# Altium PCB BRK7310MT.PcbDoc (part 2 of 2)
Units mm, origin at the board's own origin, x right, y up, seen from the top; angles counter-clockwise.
Board outline 140 x 100 mm, 6 copper layers (L1-TOP, L2-GND, L3-SIG, L4-SIG, L5-GND, L6-BOT), stack 1.39 mm thick; 75 components, 182 nets, 687 pads, 296 vias.
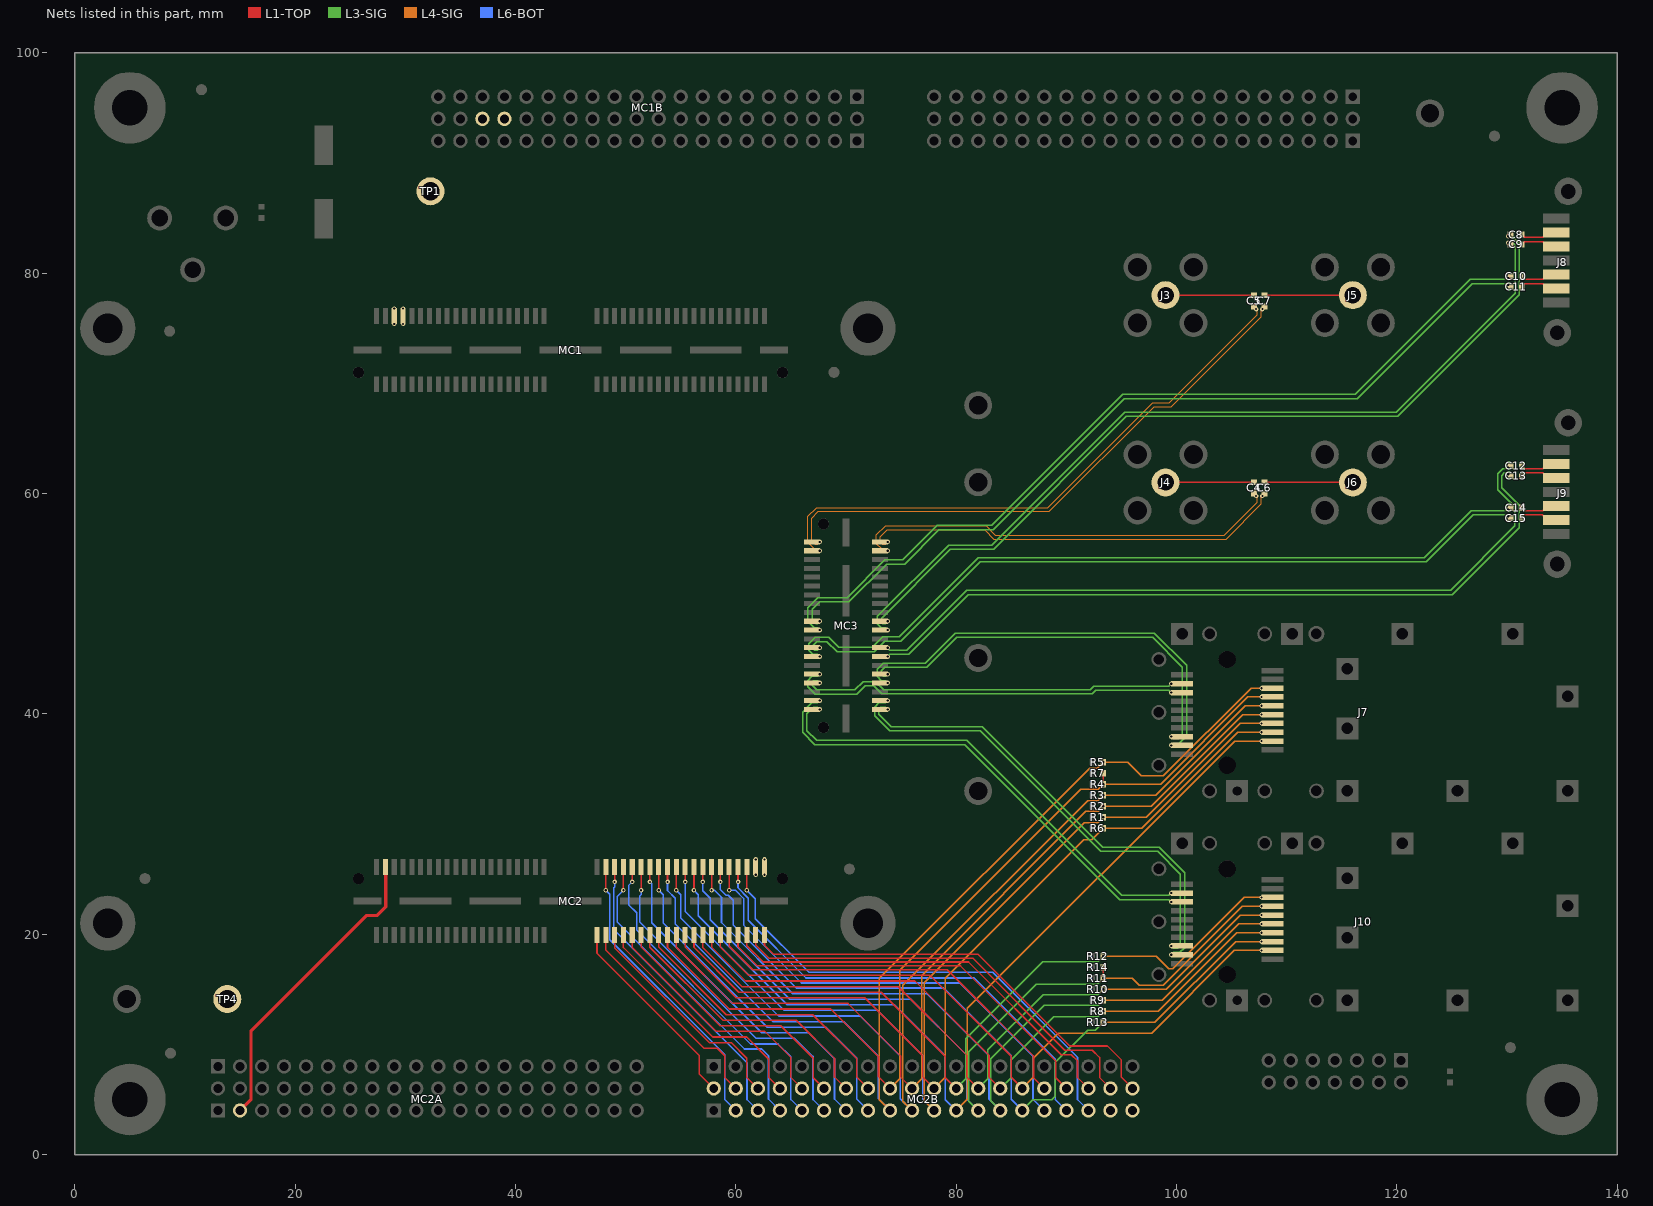
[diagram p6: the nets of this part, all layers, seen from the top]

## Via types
v1: diameter 0.406, hole 0.203, L1-TOP to L6-BOT, tented both sides, 296 vias

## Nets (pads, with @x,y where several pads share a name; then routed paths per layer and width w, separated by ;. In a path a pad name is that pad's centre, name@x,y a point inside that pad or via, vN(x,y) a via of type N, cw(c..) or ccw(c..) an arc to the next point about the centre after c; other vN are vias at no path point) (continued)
MC2_42: MC2.42 MC2B.2 | length 18.5
  L1-TOP w0.146: MC2.42@47.4,20.135 47.4,18.278 56.693,8.986 56.693,7.307 MC2B.2@58,6
MC2_43: MC2.43 MC2B.3 | length 26.8
  L1-TOP w0.146: v1(48.2,23.981) MC2.43@48.2,25.865
  L6-BOT w0.146: v1(48.2,23.981) 48.565,23.617 48.565,19.507 58.979,9.093 58.979,5.021 MC2B.3@60,4
MC2_44: MC2.44 MC2B.4 | length 19.7
  L1-TOP w0.146: MC2.44@48.2,20.135 48.2,18.555 57.103,9.652 58.322,9.652 59,8.974 59,7 MC2B.4@60,6
MC2_45: MC2.45 MC2B.5 | length 27.5
  L1-TOP w0.146: MC2.45@48.971,26.01 49,25.98 v1(49,24.743)
  L6-BOT w0.146: v1(49,24.743) 49,24.29 48.92,24.21 48.92,20.422 61.011,8.331 61.011,4.989 MC2B.5@62,4
MC2_46: MC2.46 MC2B.6 | length 20.7
  L1-TOP w0.146: MC2.46@49,20.135 49,18.745 57.586,10.16 59.592,10.16 61,8.752 61,7 MC2B.6@62,6
MC2_47: MC2.47 MC2B.7 | length 29.1
  L1-TOP w0.146: v1(49.801,23.981) MC2.47@49.801,25.865
  L6-BOT w0.146: v1(49.801,23.981) 49.225,23.406 49.225,21.133 60.782,9.576 62.361,9.576 62.967,8.97 62.967,5.033 MC2B.7@64,4
MC2_48: MC2.48 MC2B.8 | length 21.8
  L1-TOP w0.146: MC2.48@49.801,20.135 49.801,18.783 57.916,10.668 60.989,10.668 63,8.657 63,7 MC2B.8@64,6
MC2_49: MC2.49 MC2B.9 | length 30.2
  L1-TOP w0.146: MC2.49@50.571,26.06 50.601,26.031 v1(50.601,24.743)
  L6-BOT w0.146: v1(50.601,24.743) 50.267,24.409 50.267,22.683 51,21.949 51,20.374 61.341,10.033 63.834,10.033 65,8.867 65,5 MC2B.9@66,4
MC2_50: MC2.50 MC2B.10 | length 23.1
  L1-TOP w0.146: MC2.50@50.601,20.135 50.601,18.796 58.221,11.176 62.64,11.176 65,8.816 65,7 MC2B.10@66,6
MC2_51: MC2.51 MC2B.11 | length 31
  L1-TOP w0.146: v1(51.401,23.981) MC2.51@51.401,25.865
  L6-BOT w0.146: v1@51.342,24.04 v1@51.401,24.1 ; v1(51.401,23.981) 51.401,23.592 51.283,23.473 51.283,21.107 61.849,10.541 65.358,10.541 67.005,8.894 67.005,4.995 MC2B.11@68,4
MC2_52: MC2.52 MC2B.12 | length 24.2
  L1-TOP w0.146: MC2.52@51.401,20.135 51.401,18.851 58.567,11.684 64.088,11.684 67.031,8.741 67.031,6.969 MC2B.12@68,6
MC2_53: MC2.53 MC2B.13 | length 31.9
  L1-TOP w0.146: MC2.53@52.172,25.984 52.201,25.955 v1(52.201,24.743)
  L6-BOT w0.146: v1(52.201,24.743) 52.375,24.569 52.375,21.031 62.357,11.049 66.603,11.049 68.961,8.691 68.961,5.039 MC2B.13@70,4
MC2_54: MC2.54 MC2B.14 | length 25.4
  L1-TOP w0.146: MC2.54@52.201,20.135 52.201,18.821 58.83,12.192 65.485,12.192 68.961,8.716 68.961,7.039 MC2B.14@70,6
MC2_55: MC2.55 MC2B.15 | length 32.8
  L1-TOP w0.146: v1(53.001,23.981) MC2.55@53.001,25.865
  L6-BOT w0.146: v1(53.001,23.981) 53.416,23.566 53.416,21.006 62.865,11.557 68.152,11.557 70.968,8.741 70.968,5.032 MC2B.15@72,4
MC2_56: MC2.56 MC2B.16 | length 26.6
  L1-TOP w0.146: MC2.56@53.001,20.135 53.001,18.834 59.135,12.7 66.984,12.7 70.993,8.691 70.993,7.007 MC2B.16@72,6
MC2_71: MC2.71 MC2B.31 | length 42.5
  L1-TOP w0.146: v1(59.402,23.981) MC2.71@59.402,25.865
  L6-BOT w0.146: v1(59.402,23.981) 59.966,23.981 60.706,23.241 60.706,20.828 65.964,15.57 80.319,15.57 86.97,8.919 86.97,5.03 MC2B.31@88,4
MC2_72: MC2.72 MC2B.32 | length 36.3
  L1-TOP w0.146: MC2.72@59.402,20.135 59.402,18.894 61.531,16.764 79.201,16.764 87.02,8.945 87.02,6.98 MC2B.32@88,6
MC2_73: MC2.73 MC2B.33 | length 43.3
  L1-TOP w0.146: v1(60.202,24.743) 60.202,25.946 MC2.73@60.249,25.993
  L6-BOT w0.146: v1(60.202,24.743) 60.202,24.202 61.138,23.266 61.138,21.26 66.37,16.027 81.636,16.027 89.002,8.661 89.002,4.998 MC2B.33@90,4
MC2_74: MC2.74 MC2B.34 | length 37.1
  L1-TOP w0.146: MC2.74@60.202,19.914 60.202,18.868 61.951,17.12 80.391,17.12 89.027,8.484 89.027,6.973 MC2B.34@90,6
MC2_75: MC2.75 MC2B.35 | length 44.5
  L1-TOP w0.146: v1(61.002,23.981) MC2.75@61.002,25.865
  L6-BOT w0.146: v1(61.002,23.981) 61.773,23.211 61.773,21.412 66.65,16.535 83.312,16.535 91.008,8.839 91.008,4.992 MC2B.35@92,4
MC2_76: MC2.76 MC2B.36 | length 38.2
  L1-TOP w0.146: MC2.76@61.002,19.914 61.002,18.957 62.484,17.475 81.128,17.475 89.535,9.068 90.449,9.068 91.008,8.509 91.008,6.992 MC2B.36@92,6
MC2_78: MC2.78 MC2B.38 | length 39.6
  L1-TOP w0.146: MC2.78@61.802,19.914 61.802,19.021 62.992,17.831 81.509,17.831 89.865,9.474 92.354,9.474 93.015,8.814 93.015,6.985 MC2B.38@94,6
MC2_80: MC2.80 MC2B.40 | length 40.6
  L1-TOP w0.146: MC2.80@62.602,19.914 62.602,19.008 63.449,18.161 81.991,18.161 90.297,9.855 93.726,9.855 94.996,8.585 94.996,7.004 MC2B.40@96,6
MGTREFCLK0N: C4.2 MC3.38 | length 39.2
  L4-SIG w0.107: v1(73.782,54.801) 73.562,55.021 73.18,55.021 72.766,55.435 72.766,56.233 73.587,57.053 82.723,57.053 83.566,56.21 104.341,56.21 107.325,59.194 107.325,59.658 v1(107.213,59.77)
MGTREFCLK0P: C6.2 MC3.40 | length 38.6
  L4-SIG w0.107: v1(73.782,55.601) 73.562,55.381 73.33,55.381 73.127,55.584 73.127,56.083 73.736,56.693 82.573,56.693 83.417,55.85 104.491,55.85 107.686,59.045 107.686,59.658 v1(107.798,59.77)
MGTREFCLK1N: C5.2 MC3.37 | length 52.7
  L4-SIG w0.107: v1(67.61,54.801) 67.39,55.021 67.059,55.021 66.518,55.562 66.518,57.909 67.333,58.725 88.316,58.725 97.82,68.229 99.355,68.229 107.325,76.2 107.325,76.625 v1(107.213,76.737)
MGTREFCLK1P: C7.2 MC3.39 | length 52.1
  L4-SIG w0.107: v1(67.61,55.601) 67.39,55.381 67.208,55.381 66.878,55.711 66.878,57.76 67.483,58.364 88.465,58.364 97.97,67.869 99.504,67.869 107.686,76.051 107.686,76.625 v1(107.798,76.737)
NetC4_1: C4.1 J4.1 | length 8
  L1-TOP w0.133: J4.1@99,61 99.017,61.017 C4.1@107.036,61.017
NetC5_1: C5.1 J3.1 | length 8
  L1-TOP w0.133: J3.1@99,78 99.016,77.984 C5.1@107.036,77.984
NetC6_1: C6.1 J6.1 | length 8
  L1-TOP w0.133: C6.1@107.975,61.017 115.983,61.017 J6.1@116,61
NetC7_1: C7.1 J5.1 | length 8
  L1-TOP w0.133: C7.1@107.975,77.984 115.984,77.984 J5.1@116,78
SATA_1_TXA+: C8.2 MC3.22 | length 77.1
  L3-SIG w0.127: v1(73.782,48.4) 73.573,48.191 73.349,48.191 73.228,48.311 73.228,48.692 79.477,54.94 83.388,54.94 95.453,67.005 120.097,67.005 131.115,78.023 131.115,82.682 130.561,83.236 130.218,83.236 v1(130.104,83.35)
SATA_1_TXA+_C: C8.1 J8.2 | length 3.4
  L1-TOP w0.133: C8.1@131.328,83.502 131.589,83.241 133.228,83.241 133.672,83.685 J8.2@134.45,83.685
SATA_1_TXA-: C9.2 MC3.20 | length 77.1
  L3-SIG w0.127: v1(73.782,47.6) 73.573,47.81 73.191,47.81 72.847,48.153 72.847,48.85 79.319,55.321 83.23,55.321 95.295,67.386 119.939,67.386 130.734,78.181 130.734,82.524 130.404,82.855 130.218,82.855 v1(130.104,82.74)
SATA_1_TXA-_C: C9.1 J8.3 | length 3.4
  L1-TOP w0.133: C9.1@131.328,82.605 131.582,82.86 133.218,82.86 133.663,82.415 J8.3@134.45,82.415
SATA_1_TXB+: C11.2 MC3.21 | length 77.3
  L3-SIG w0.127: v1(67.61,48.4) 67.4,48.191 67.285,48.191 66.929,48.546 66.929,49.479 67.615,50.165 70.261,50.165 73.69,53.594 75.316,53.594 78.441,56.718 83.368,56.718 95.255,68.605 116.388,68.605 126.823,79.041 129.985,79.041 v1(130.104,78.922)
SATA_1_TXB+_C: C11.1 J8.6 | length 3.4
  L1-TOP w0.133: C11.1@131.328,78.778 131.599,79.05 133.244,79.05 133.688,78.605 J8.6@134.45,78.605
SATA_1_TXB-: C10.2 MC3.19 | length 78.6
  L3-SIG w0.127: v1(67.61,47.6) 67.4,47.81 67.127,47.81 66.548,48.388 66.548,49.637 67.457,50.546 70.104,50.546 73.533,53.975 75.159,53.975 78.283,57.099 83.21,57.099 95.098,68.986 116.23,68.986 126.666,79.422 129.985,79.422 v1(130.104,79.54)
SATA_1_TXB-_C: C10.1 J8.5 | length 3.4
  L1-TOP w0.133: C10.1@131.328,79.692 131.589,79.431 133.228,79.431 133.672,79.875 J8.5@134.45,79.875
SATA_2_TXA+: C12.2 MC3.16 | length 68.3
  L3-SIG w0.127: v1(73.782,46) 73.992,45.79 75.534,45.79 80.95,51.206 124.866,51.206 130.708,57.048 130.708,58.776 129.134,60.35 129.134,61.778 129.598,62.243 129.987,62.243 v1(130.104,62.36)
SATA_2_TXA+_C: C12.1 J9.2 | length 3.4
  L1-TOP w0.133: C12.1@131.328,62.512 131.6,62.241 133.234,62.241 133.678,62.685 J9.2@134.45,62.685
SATA_2_TXA-: C13.2 MC3.14 | length 68.3
  L3-SIG w0.127: v1(73.782,45.2) 73.992,45.409 75.691,45.409 81.108,50.825 125.024,50.825 131.089,56.891 131.089,58.933 129.515,60.508 129.515,61.62 129.756,61.862 129.987,61.862 v1(130.104,61.745)
SATA_2_TXA-_C: C13.1 J9.3 | length 3.4
  L1-TOP w0.133: C13.1@131.328,61.598 131.589,61.86 133.238,61.86 133.682,61.415 J9.3@134.45,61.415
SATA_2_TXB+: C15.2 MC3.15 | length 69.8
  L3-SIG w0.127: v1(67.61,46) 67.4,45.79 67.158,45.79 67,45.949 67,46.197 67.361,46.558 68.275,46.558 69.19,45.644 72.548,45.644 73.513,46.609 74.986,46.609 82.174,53.797 122.662,53.797 126.92,58.055 129.989,58.055 v1(130.104,57.94)
SATA_2_TXB+_C: C15.1 J9.6 | length 3.4
  L1-TOP w0.133: C15.1@131.328,57.763 131.615,58.05 133.212,58.05 133.657,57.605 J9.6@134.45,57.605
SATA_2_TXB-: C14.2 MC3.13 | length 71.1
  L3-SIG w0.127: v1(67.61,45.2) 67.4,45.409 67.001,45.409 66.619,45.791 66.619,46.355 67.203,46.939 68.433,46.939 69.347,46.025 72.39,46.025 73.355,46.99 74.828,46.99 82.017,54.178 122.504,54.178 126.762,58.436 129.989,58.436 v1(130.104,58.55)
SATA_2_TXB-_C: C14.1 J9.5 | length 3.4
  L1-TOP w0.133: C14.1@131.328,58.702 131.6,58.431 133.259,58.431 133.703,58.875 J9.5@134.45,58.875
SFP1_LOS: J7.8 MC2.57 MC2B.17 R5.2 | length 93.2
  L1-TOP w0.146: MC2.57@53.797,26.031 53.801,26.027 v1(53.801,24.743)
  L4-SIG w0.124: MC2B.17@74,4 73.025,4.975 73.025,16.006 92.1,35.081 92.809,35.081 v1(93.345,35.617) 95.552,35.617 96.799,34.37 98.81,34.37 106.77,42.33 v1(107.717,42.33)
  L6-BOT w0.146: v1(53.801,24.743) 53.801,23.969 54.508,23.261 54.508,20.93 63.373,12.065 69.803,12.065 72.949,8.919 72.949,5.051 MC2B.17@74,4
SFP1_MOD_DEF_0: J7.6 MC2.59 MC2B.19 R3.2 | length 89.8
  L1-TOP w0.146: v1(54.601,23.981) MC2.59@54.601,25.865
  L4-SIG w0.124: MC2B.19@76,4 75.159,4.841 75.159,15.345 91.923,32.109 92.837,32.109 v1(93.345,32.617) 98.124,32.617 106.237,40.73 v1(107.717,40.73)
  L6-BOT w0.146: v1(54.601,23.981) 54.991,23.592 54.991,21.463 63.881,12.573 71.302,12.573 74.93,8.945 74.93,5.07 MC2B.19@76,4
SFP1_MOD_DEF_1: J7.5 MC2.60 MC2B.20 R2.2 | length 80.4
  L1-TOP w0.146: MC2.60@54.601,20.135 54.601,18.809 59.694,13.716 70.184,13.716 74.955,8.945 74.955,7.045 MC2B.20@76,6
  L4-SIG w0.124: MC2B.20@76,6 76.86,6.86 76.86,16.234 91.77,31.144 92.872,31.144 v1(93.345,31.617) 97.708,31.617 106.021,39.93 v1(107.717,39.93)
SFP1_MOD_DEF_2: J7.4 MC2.61 MC2B.21 R1.2 | length 88.8
  L1-TOP w0.146: v1(55.401,24.743) 55.401,26.09 MC2.61@55.448,26.137
  L4-SIG w0.124: MC2B.21@78,4 77.114,4.886 77.114,15.599 91.618,30.103 92.83,30.103 v1(93.345,30.617) 97.267,30.617 105.78,39.13 v1(107.717,39.13)
  L6-BOT w0.146: v1(55.401,24.743) 55.401,22.066 64.386,13.081 72.876,13.081 76.962,8.995 76.962,5.038 MC2B.21@78,4
SFP1_RATE_SELECT: J7.7 MC2.58 MC2B.18 R4.2 R7.1 | length 83.1
  L1-TOP w0.146: MC2.58@53.801,20.135 53.801,18.821 59.414,13.208 68.609,13.208 72.949,8.868 72.949,7.051 MC2B.18@74,6 ; v1(93.345,33.617) R7.1@93.345,34.617
  L4-SIG w0.124: MC2B.18@74,6 74.879,6.879 74.879,16.742 91.288,33.151 92.878,33.151 v1(93.345,33.617) 98.565,33.617 106.478,41.53 v1(107.717,41.53)
SFP1_RD_N: J7.12 MC3.7 | length 34.7
  L3-SIG w0.127: v1(67.61,42.799) 67.4,43.009 67.057,43.009 66.898,42.85 66.898,42.627 67.361,42.164 70.815,42.164 71.577,42.926 72.669,42.926 73.406,42.189 92.176,42.189 92.507,42.52 99.308,42.52 v1(99.517,42.73)
SFP1_RD_P: J7.13 MC3.9 | length 36
  L3-SIG w0.127: v1(67.61,43.599) 67.4,43.39 66.899,43.39 66.517,43.008 66.517,42.469 67.203,41.783 69.476,41.783 70.973,41.783 71.735,42.545 72.512,42.545 73.248,41.808 92.334,41.808 92.665,42.139 99.308,42.139 v1(99.517,41.93)
SFP1_TD_N: J7.19 MC3.8 | length 40.7
  L3-SIG w0.127: v1(73.782,42.799) 73.573,43.009 73.216,43.009 72.822,43.403 72.822,44.049 73.375,44.602 77.191,44.602 79.908,47.32 97.999,47.32 100.914,44.405 100.914,37.993 100.263,37.341 99.729,37.341 v1(99.517,37.13)
SFP1_TD_P: J7.18 MC3.10 | length 38.2
  L3-SIG w0.127: v1(73.782,43.599) 73.573,43.39 73.374,43.39 73.203,43.561 73.203,43.891 73.533,44.221 77.348,44.221 80.066,46.939 97.841,46.939 100.533,44.247 100.533,38.151 100.105,37.722 99.729,37.722 v1(99.517,37.934)
SFP1_TDIS: J7.3 MC2.62 MC2B.22 R6.1 | length 78.7
  L1-TOP w0.146: MC2.62@55.401,20.135 55.401,18.838 60.015,14.224 71.708,14.224 76.962,8.97 76.962,7.038 MC2B.22@78,6
  L4-SIG w0.124: MC2B.22@78,6 78.994,6.994 78.994,16.006 91.567,28.579 92.306,28.579 v1(93.345,29.617) 96.826,29.617 105.538,38.33 v1(107.717,38.33)
SFP1_TFAULT: J7.2 MC2.63 MC2B.23 | length 83.9
  L1-TOP w0.146: v1(56.201,23.981) MC2.63@56.201,25.865
  L4-SIG w0.124: MC2B.23@80,4 81.001,5.001 81.001,13.259 105.272,37.53 v1(107.717,37.53)
  L6-BOT w0.146: v1(56.201,23.981) 56.591,23.592 56.591,21.67 64.672,13.589 74.4,13.589 79.019,8.97 79.019,4.981 MC2B.23@80,4
SFP2_LOS: J10.8 MC2.64 MC2B.24 R12.2 | length 69.5
  L1-TOP w0.146: MC2.64@56.201,20.135 56.201,18.809 60.278,14.732 73.207,14.732 79.019,8.919 79.019,6.981 MC2B.24@80,6
  L3-SIG w0.124: MC2B.24@80,6 80.874,6.874 80.874,10.519 87.859,17.504 92.842,17.504 v1(93.345,18.007)
  L4-SIG w0.124: v1(93.345,18.007) 98.147,18.007 99.289,16.866 99.67,16.866 106.134,23.33 v1(107.717,23.33)
SFP2_MOD_DEF_0: J10.6 MC2.66 MC2B.26 R10.2 | length 66.6
  L1-TOP w0.146: MC2.66@57.001,20.135 57.001,18.796 60.557,15.24 74.731,15.24 80.975,8.995 80.975,7.025 MC2B.26@82,6
  L3-SIG w0.124: MC2B.26@82,6 82.88,6.88 82.88,9.503 87.884,14.507 92.845,14.507 v1(93.345,15.007)
  L4-SIG w0.124: v1(93.345,15.007) 99.081,15.007 105.804,21.73 v1(107.717,21.73)
SFP2_MOD_DEF_1: J10.5 MC2.67 MC2B.27 R9.2 | length 74.7
  L1-TOP w0.146: v1(57.802,23.981) MC2.67@57.802,25.865
  L3-SIG w0.124: MC2B.27@84,4 83.134,4.866 83.134,8.691 87.986,13.542 92.88,13.542 v1(93.345,14.007)
  L4-SIG w0.124: v1(93.345,14.007) 98.716,14.007 105.639,20.93 v1(107.717,20.93)
  L6-BOT w0.146: v1(57.802,23.981) 58.067,23.981 58.699,23.349 58.699,21.057 65.163,14.593 77.359,14.593 82.982,8.97 82.982,5.018 MC2B.27@84,4
SFP2_MOD_DEF_2: J10.4 MC2.68 MC2B.28 R8.2 | length 64.5
  L1-TOP w0.146: MC2.68@57.802,20.135 57.802,18.834 60.888,15.748 76.255,15.748 82.982,9.021 82.982,7.018 MC2B.28@84,6
  L3-SIG w0.124: MC2B.28@84,6 84.988,6.988 84.988,8.614 88.875,12.501 92.846,12.501 v1(93.345,13)
  L4-SIG w0.124: v1(93.345,13) 98.319,13 105.449,20.13 v1(107.717,20.13)
SFP2_RATE_SELECT: J10.7 MC2.65 MC2B.25 R11.2 R14.1 | length 78.1
  L1-TOP w0.146: MC2.65@56.998,26.086 57.001,26.082 v1(57.001,24.743) ; v1(93.345,16.007) R14.1@93.345,17.007
  L3-SIG w0.124: MC2B.25@82,4 81.153,4.847 81.153,9.351 87.274,15.472 92.81,15.472 v1(93.345,16.007)
  L4-SIG w0.124: v1(93.345,16.007) 95.985,16.007 96.625,15.367 98.806,15.367 105.969,22.53 v1(107.717,22.53)
  L6-BOT w0.146: v1(57.001,24.743) 57.001,23.952 57.683,23.27 57.683,21.311 64.897,14.097 75.874,14.097 80.975,8.995 80.975,5.025 MC2B.25@82,4
SFP2_RD_N: J10.12 MC3.1 | length 42.4
  L3-SIG w0.127: v1(67.61,40.399) 67.4,40.609 67.055,40.609 66.446,40 66.446,38.481 67.341,37.587 80.955,37.587 95.021,23.52 99.308,23.52 v1(99.517,23.73)
SFP2_RD_P: J10.13 MC3.3 | length 43.6
  L3-SIG w0.127: v1(67.61,41.199) 67.4,40.99 66.898,40.99 66.065,40.157 66.065,38.323 67.183,37.206 80.797,37.206 94.863,23.139 99.308,23.139 v1(99.517,22.93)
SFP2_TD_N: J10.19 MC3.2 | length 43.4
  L3-SIG w0.127: v1(73.782,40.399) 73.573,40.609 73.146,40.609 72.974,40.437 72.974,39.98 74.117,38.837 82.347,38.837 93.294,27.889 98.43,27.889 100.736,25.583 100.736,18.791 100.287,18.341 99.729,18.341 v1(99.517,18.13)
SFP2_TD_P: J10.18 MC3.4 | length 43.5
  L3-SIG w0.127: v1(73.782,41.199) 73.573,40.99 72.988,40.99 72.593,40.595 72.593,39.822 73.959,38.456 82.189,38.456 83.103,37.541 ; 83.055,37.493 83.103,37.541 ; v1(99.517,18.934) 99.729,18.722 100.129,18.722 100.355,18.948 100.355,25.425 98.273,27.508 93.136,27.508 83.103,37.541
SFP2_TDIS: J10.3 MC2.69 MC2B.29 R13.1 | length 71.2
  L1-TOP w0.146: v1(58.602,24.743) 58.602,25.946 MC2.69@58.649,25.993
  L3-SIG w0.124: MC2B.29@86,4 86.97,4.97 88.663,4.97 89.002,5.309 89.002,8.357 91.932,11.287 92.625,11.287 v1(93.345,12.007)
  L4-SIG w0.124: v1(93.345,12.007) 98.037,12.007 105.36,19.33 v1(107.717,19.33)
  L6-BOT w0.146: v1(58.602,24.743) 58.602,24.025 59.103,23.524 59.312,23.524 59.766,23.07 59.766,20.828 65.481,15.113 78.871,15.113 84.988,8.995 84.988,5.012 MC2B.29@86,4
SFP2_TFAULT: J10.2 MC2.70 MC2B.30 | length 63.1
  L1-TOP w0.146: MC2.70@58.602,20.135 58.602,18.821 61.167,16.256 77.652,16.256 84.988,8.919 84.988,7.012 MC2B.30@86,6
  L4-SIG w0.124: MC2B.30@86,6 86.995,6.995 86.995,8.741 89.281,11.027 97.739,11.027 105.242,18.53 v1(107.717,18.53)
VCCBATT_0: MC2.3 MC2A.3 | length 28.1
  L1-TOP w0.305: MC2A.3@15,4 16.002,5.002 16.002,11.246 26.447,21.692 27.432,21.692 28.219,22.479 28.219,26.065 MC2.3@28.198,26.086
VCCO_MC1: MC1.74 MC1.76 MC1B.34 MC1B.36 TP1.1
  other v1: 28.998,75.388 29.798,75.388 28.998,76.784 29.798,76.784
VCCO_MC2: MC2.77 MC2.79 MC2B.37 MC2B.39 TP4.1
  other v1: 61.802,25.388 62.602,25.388 61.802,26.784 62.602,26.784
pads on no net: FID1.FID? FID2.FID? FID3.FID? FID4.FID? FID5.FID? FID6.FID? FID7.FID? FID8.FID? J1.12 J1.14 J2.3 J7.0 J7.MH J8.MH J9.MH J10.0 J10.MH MC1.MH MC2.MH MC2A.5 MC2A.7 MC2A.8 MC2A.9 MC3.25 MC3.27 MC3.31 MC3.32 MC3.33 MC3.34 MC3.MH MH1.1 MH2.1 MH3.1 MH4.1 MH5.1 MH6.1 MH7.1 MH8.1

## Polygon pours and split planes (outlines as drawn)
+1.8VDD on L4-SIG "L4_+1.8VDD" (solid, pour order 203): 117.094,2.874 117.094,41.304 131.877,56.087 131.877,83.795 129.54,83.795 122.991,77.245 106.971,77.245 100.202,70.476 95.241,70.476 84.357,59.592 28.423,59.592 28.423,76.001 38.139,76.001 38.139,98.657 104.863,98.657 125.933,98.657 133.582,91.008 138.836,91.008 138.836,16.006 125.705,2.874
VCCO_MC1 on L4-SIG "L4_VCCO_MC1" (solid, pour order 202): 39.688,94.64 39.688,72.089 28.423,72.089 28.423,94.64
+VDCIN on L3-SIG "L3_+VDCIN" (solid, pour order 201): 12.344,97.358 12.344,64.389 83.845,64.389 83.845,70.993 70.612,70.993 44.247,97.358
VCCO_MC2 on L3-SIG "L3_VCCO_MC2" (solid, pour order 206): 11.557,0.813 11.557,27.305 68.656,27.305 68.656,2.995 90.68,2.995 92.685,5 98.787,5 98.787,0.813
DGND on L2-GND "L2-DGND" (solid, pour order 200): 0.508,0.5 0.508,99.5 139.5,99.5 139.5,0.5
DGND on L5-GND "L5-DGND" (solid, pour order 204): 0.508,0.5 0.508,99.5 139.5,99.5 139.5,0.5
+3.3VDD on L6-BOT "L6_+3.3VDD" (solid, pour order 205): 90.957,12.395 103.454,12.395 103.454,67.158 37.262,67.158 32.322,72.098 32.322,79.362 45.406,92.447 45.406,96.952 11.328,96.952 11.328,5.08 22.136,5.08 22.136,11.9 29.235,18.999 29.235,25.556 60.579,25.556 77.796,25.556

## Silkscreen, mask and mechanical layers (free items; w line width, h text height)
Top Overlay:
  lines w0.2: 6,18 69,18 ; 6,78 69,78 ; 75,24 75,72
  lines w0.508: 93,54 93,67 122,67 122,54 93,54 ; 93,71 122,71 122,84 93,84 93,71
  text "DGND" at 28.887,91.585 h0.76
  text "DGND" at 73.887,91.585 h0.76
  text "SATA 1" at 127,84.607 h1.27 r270
  text "'.Part_Number' / '.PCB_Revision'XX '.PCB_Date_Code'" at 74.916,79.746 h1.02
  text "SATA 2" at 127,64.059 h1.27 r270
  text "SFP 1" at 95.479,42.752 h1.27 r270
  text "SFP 2" at 95.479,23.956 h1.27 r270
  text "DGND" at 97.409,7.725 h0.76
  text "DGND" at 52.434,7.656 h0.76
  text "4:TMS" at 116.402,1.172 h0.76 r45
  text "8:TDO" at 112.261,1.121 h0.76 r45
  text "6:TCK" at 114.293,1.096 h0.76 r45
  text "10:TDI" at 109.95,0.817 h0.76 r45
  text "2:Vref" at 118.078,0.74 h0.76 r45
Dimensions:
  text ":::" at 30.556,102.446 h1.27 r180
  text ":::" at 100.635,101.6 h1.27
  text ":::" at 141.122,71.552 h1.27 r270
  text ":::" at -0.991,63.068 h1.27 r90
  text ":::" at -1.27,24.968 h1.27 r90
  text ":::" at 141.173,10.693 h1.27 r270
  text ":::" at 30.556,-1.168 h1.27 r180
  text ":::" at 102.972,-1.168 h1.27 r180
Outline:
  the board outline again, w0.203
Fab Notes:
  drawing of 409 lines, arcs and shapes, not listed
  text "CONTROLLED IMPEDANCE TABLE" at 102.692,190.758 h1.27
  text "Layer" at 103.89,186.44 h1.27
  text "Width / (mils)" at 130.56,185.424 h1.27
  text "Impedance / (ohms)" at 114.05,185.17 h1.27
  text "Spacing / (mils)" at 139.958,185.17 h1.27
  text "L1" at 105.414,182.604 h1.14
  text "50 Single" at 114.558,182.604 h1.14
  text "5.75" at 131.83,182.604 h1.14
  text "-" at 141.228,182.376 h1.14
  text "L1" at 105.414,180.064 h1.14
  text "100 Diff" at 114.558,180.064 h1.14
  text "5.25" at 131.83,180.064 h1.14
  text "-" at 141.228,180.064 h1.14
  text "L3" at 105.414,177.524 h1.14
  text "100 Diff" at 114.558,177.524 h1.14
  text "5.00" at 131.83,177.524 h1.14
  text "10.00" at 141.228,177.524 h1.14
  text "L5" at 105.414,174.984 h1.14
  text "50 Single" at 114.558,174.984 h1.14
  text "5.75" at 131.83,174.984 h1.14
  text "-" at 141.228,174.984 h1.14
  text "NOTES: /  / 1. MATERIAL SELECTION: /      6-LAYER, IT-180A OR EQUIVALENT, 62 MILS +/-10% THICK /      SURFACE FINISH: ENIG (ELECTROLESS NICKEL, IMMERSION GOLD) /  / 2. SOLDER RESIST: BLUE LPI /  / 3. SILKSCREEN: WHITE / DO NOT REMOVE OVER TENTED VIAS /  / 4. LOT CODE IDENTIFICATION: ADD TO SILKSCREEN /      FORMAT: YYWW (YY = 2-DIGIT YEAR, WW = 2-DIGIT WEEK) /       / 5. DRILL SIZES ARE FINISHED SIZE AFTER PLATING /  / 6. ELECTRICAL BARE BOARD TEST REQUIRED /  / 7. BOARD TO BE IMPEDANCE CONTROLLED. /      SEE CONTROLLED IMPEDANCE TABLE /      REFER TO '.Assembly_Part_Num'-PCBStackup.pdf /      SHORT TRACE IMPEDANCE MEASUREMENTS CAN DEFAULT TO TDR COUPONS /   / 8. PANELIZATION: /      2 PIECES PER ARRAY /      TAB ROUTING REQUIRED /      TAB LOCATIONS INDICATED BY ::: /      0.25-INCH RAILS ON ALL SIDES /       / 9. ALL 8.0-MIL VIAS MUST BE PLATED OVER FILLED VIA (POFV) /  / 10. FABRICATE TO MEET EU ROHS DIRECTIVE. /      SUPPLIER TO ADD LEAD-FREE MARKING IN SILKSCREEN. /       / 11. UL CERTIFICATION MARK REQUIRED" at -43.993,152.248 h1.27
  text "LAYER STACKUP TABLE" at 192.075,108.991 h1.27
  text "Layer" at 193.158,105.623 h1.27
  text "Name" at 201.818,105.623 h1.27
  text "Material" at 221.481,105.623 h1.27
  text "Thickness" at 239.662,105.623 h1.27
  text "Constant" at 253.4,105.623 h1.27
  text "Board Layer Stack" at 265.445,105.623 h1.27
  text "1" at 193.158,103.083 h1.27
  text "Top Overlay" at 201.818,103.083 h1.27
  text "2" at 193.158,100.543 h1.27
  text "Top Solder" at 201.818,100.543 h1.27
  text "Solder Resist" at 221.481,100.543 h1.27
  text "0.80mil" at 239.662,100.543 h1.27
  text "0" at 253.4,100.543 h1.27
  text "3" at 193.158,98.003 h1.27
  text "L1-TOP" at 201.818,98.003 h1.27
  text "Copper" at 221.481,98.003 h1.27
  text "1.40mil" at 239.662,98.003 h1.27
  text "4" at 193.158,95.463 h1.27
  text "Dielectric 2" at 201.818,95.463 h1.27
  text "IT180A" at 221.481,95.463 h1.27
  text "4.37mil" at 239.662,95.463 h1.27
  text "4.12" at 253.4,95.463 h1.27
  text "5" at 193.158,92.923 h1.27
  text "L2-GND" at 201.818,92.923 h1.27
  text "Copper" at 221.481,92.923 h1.27
  text "1.40mil" at 239.662,92.923 h1.27
  text "6" at 193.158,90.383 h1.27
  text "Dielectric 5" at 201.818,90.383 h1.27
  text "IT180A" at 221.481,90.383 h1.27
  text "2.30mil" at 239.662,90.383 h1.27
  text "4.12" at 253.4,90.383 h1.27
  text "7" at 193.158,87.843 h1.27
  text "L3-SIG" at 201.818,87.843 h1.27
  text "Copper" at 221.481,87.843 h1.27
  text "1.40mil" at 239.662,87.843 h1.27
  text "8" at 193.158,85.303 h1.27
  text "Dielectric 6" at 201.818,85.303 h1.27
  text "IT180A" at 221.481,85.303 h1.27
  text "32.99mil" at 239.662,85.303 h1.27
  text "4.2" at 253.4,85.303 h1.27
  text "9" at 193.158,82.763 h1.27
  text "L4-SIG" at 201.818,82.763 h1.27
  text "Copper" at 221.481,82.763 h1.27
  text "1.40mil" at 239.662,82.763 h1.27
  text "10" at 193.158,80.223 h1.27
  text "Dielectric 1" at 201.818,80.223 h1.27
  text "IT180A" at 221.481,80.223 h1.27
  text "2.30mil" at 239.662,80.223 h1.27
  text "4.12" at 253.4,80.223 h1.27
  text "11" at 193.158,77.683 h1.27
  text "L5-GND" at 201.818,77.683 h1.27
  text "Copper" at 221.481,77.683 h1.27
  text "1.40mil" at 239.662,77.683 h1.27
  text "12" at 193.158,75.143 h1.27
  text "Dielectric 4" at 201.818,75.143 h1.27
  text "IT180A" at 221.481,75.143 h1.27
  text "4.37mil" at 239.662,75.143 h1.27
  text "4.12" at 253.4,75.143 h1.27
  text "13" at 193.158,72.603 h1.27
  text "L6-BOT" at 201.818,72.603 h1.27
  text "Copper" at 221.481,72.603 h1.27
  text "1.40mil" at 239.662,72.603 h1.27
  text "14" at 193.158,70.063 h1.27
  text "Solder Side" at 201.818,70.063 h1.27
  text "Solder Resist" at 221.481,70.063 h1.27
  text "0.80mil" at 239.662,70.063 h1.27
  text "0" at 253.4,70.063 h1.27
  text "15" at 193.158,67.523 h1.27
  text "Bottom Overlay" at 201.818,67.523 h1.27
Assy Notes Top:
  text "NOTES" at -6.045,112.497 h1.02
  text "1. SOLDER SHIELD1 AND SHIELD2 IN 8 PLACES ON BOTTOM SIDE AS INDICATED." at -6.172,109.271 h1.02
Assy Notes Bot:
  circle w0.254: c105.512,14.072 r1.88
  circle w0.254: c130.505,28.27 r1.88
  circle w0.254: c130.558,47.324 r1.88
  circle w0.254: c135.509,33.045 r1.88
  circle w0.254: c100.482,47.244 r1.88
  circle w0.254: c105.486,32.944 r1.88
  circle w0.254: c100.508,28.296 r1.88
  circle w0.254: c135.56,14.021 r1.88
  lines w0.254: 131.821,48.826 133.98,50.985 141.097,50.985
  text "SOLDER ON BOTTOM SIDE / (8 PLACES)" at 172.617,44.383 h1.74
Drill Drawing:
  circle w0.203: c178.101,195.781 r0.706
  circle w0.203: c178.101,179.906 r0.423
  circle w0.203: c178.101,179.906 r0.706
  lines w0.203: 177.395,156.976 178.806,156.976 178.806,158.387 177.395,158.387 177.395,156.976 ; 177.395,160.151 178.806,160.151 178.806,161.562 177.395,161.562 177.395,160.151 ; 177.395,163.679 177.748,163.679 177.748,163.326 178.453,163.326 178.453,163.679 178.806,163.679 178.806,164.384 178.453,164.384 178.453,164.737 177.748,164.737 177.748,164.384 177.395,164.384 177.395,163.679 ; 177.395,169.676 177.395,170.029 177.748,170.381 177.395,170.734 177.395,171.087 177.748,171.087 178.101,170.734 178.453,171.087 178.806,171.087 178.806,170.734 178.453,170.381 178.806,170.029 178.806,169.676 178.453,169.676 178.101,170.029 177.748,169.676 177.395,169.676 ; 177.395,173.204 177.748,173.204 178.101,172.851 178.453,173.204 178.806,173.204 178.453,173.556 178.806,173.909 178.453,173.909 178.101,174.262 177.748,173.909 177.395,173.909 177.748,173.556 177.395,173.204 ; 177.395,176.026 178.101,176.379 178.806,176.026 178.453,176.731 178.806,177.437 178.101,177.084 177.395,177.437 177.748,176.731 177.395,176.026 ; 177.395,183.787 178.806,183.787 178.101,182.376 177.395,183.787 ; 177.395,189.431 178.101,188.726 178.806,189.431 178.101,190.137 177.395,189.431 ; 177.395,192.254 177.748,192.254 177.748,191.901 178.453,191.901 178.453,192.254 178.806,192.254 178.806,192.959 178.453,192.959 178.453,193.312 177.748,193.312 177.748,192.959 177.395,192.959 177.395,192.254 ; 177.677,157.258 178.524,157.258 178.524,158.105 177.677,158.105 177.677,157.258 ; 177.677,163.82 177.889,163.82 177.889,163.608 178.312,163.608 178.312,163.82 178.524,163.82 178.524,164.243 178.312,164.243 178.312,164.455 177.889,164.455 177.889,164.243 177.677,164.243 177.677,163.82 ; 177.677,173.345 177.889,173.345 178.101,173.133 178.312,173.345 178.524,173.345 178.312,173.556 178.524,173.768 178.312,173.768 178.101,173.98 177.889,173.768 177.677,173.768 177.889,173.556 177.677,173.345
  lines w0.254: 176.132,156.023 323.03,156.023 ; 176.132,200.473 323.03,200.473 ; 187.765,152.848 187.765,203.648 ; 200.445,152.848 200.445,203.648 ; 224.762,152.848 224.762,203.648 ; 235.443,152.848 235.443,203.648 ; 250.948,152.848 250.948,203.648 ; 276.102,152.848 276.102,203.648 ; 288.56,152.848 288.56,203.648 ; 304.319,152.848 304.319,203.648 ; 176.132,152.848 323.03,152.848 323.03,203.648 176.132,203.648 176.132,152.848
  text "DRILL TABLE" at 176.886,205.359 h1.27
  text "Symbol" at 178.037,201.426 h1.52
  text "Count" at 188.718,201.426 h1.52
  text "Hole Size" at 201.397,201.426 h1.52
  text "Plated" at 225.715,201.426 h1.52
  text "Hole Type" at 236.396,201.426 h1.52
  text "Drill Layer Pair" at 251.901,201.426 h1.52
  text "Via/Pad" at 277.055,201.426 h1.52
  text "Pad Shape" at 289.513,201.426 h1.52
  text "Template" at 305.272,201.426 h1.52
  text "2" at 188.718,198.251 h1.27
  text "33.47mil (0.850mm)" at 201.397,198.251 h1.27
  text "PTH" at 225.715,198.251 h1.27
  text "Round" at 236.396,198.251 h1.27
  text "L1-TOP - L6-BOT" at 251.901,198.251 h1.27
  text "Pad" at 277.055,198.251 h1.27
  text "Rectangle" at 289.513,198.251 h1.27
  text "s200h85" at 305.272,198.251 h1.27
  text "D" at 177.427,198.048 h1.41
  text "3" at 188.718,195.076 h1.27
  text "59.06mil (1.500mm)" at 201.397,195.076 h1.27
  text "PTH" at 225.715,195.076 h1.27
  text "Round" at 236.396,195.076 h1.27
  text "L1-TOP - L6-BOT" at 251.901,195.076 h1.27
  text "Pad" at 277.055,195.076 h1.27
  text "Rounded" at 289.513,195.076 h1.27
  text "c225h150" at 305.272,195.076 h1.27
  text "4" at 188.718,191.901 h1.27
  text "53.15mil (1.350mm)" at 201.397,191.901 h1.27
  text "PTH" at 225.715,191.901 h1.27
  text "Round" at 236.396,191.901 h1.27
  text "L1-TOP - L6-BOT" at 251.901,191.901 h1.27
  text "Pad" at 277.055,191.901 h1.27
  text "Rounded" at 289.513,191.901 h1.27
  text "c250h135" at 305.272,191.901 h1.27
  text "4" at 188.718,188.726 h1.27
  text "59.00mil (1.499mm)" at 201.397,188.726 h1.27
  text "PTH" at 225.715,188.726 h1.27
  text "Round" at 236.396,188.726 h1.27
  text "L1-TOP - L6-BOT" at 251.901,188.726 h1.27
  text "Pad" at 277.055,188.726 h1.27
  text "Rounded" at 289.513,188.726 h1.27
  text "c254h150" at 305.272,188.726 h1.27
  text "4" at 188.718,185.551 h1.27
  text "61.02mil (1.550mm)" at 201.397,185.551 h1.27
  text "NPTH" at 225.715,185.551 h1.27
  text "Round" at 236.396,185.551 h1.27
  text "L1-TOP - L6-BOT" at 251.901,185.551 h1.27
  text "Pad" at 277.055,185.551 h1.27
  text "Rounded" at 289.513,185.551 h1.27
  text "c155hn155" at 305.272,185.551 h1.27
  text "C" at 177.427,185.348 h1.41
  text "4" at 188.718,182.376 h1.27
  text "106.30mil (2.700mm)" at 201.397,182.376 h1.27
  text "PTH" at 225.715,182.376 h1.27
  text "Round" at 236.396,182.376 h1.27
  text "L1-TOP - L6-BOT" at 251.901,182.376 h1.27
  text "Pad" at 277.055,182.376 h1.27
  text "Rounded" at 289.513,182.376 h1.27
  text "c500h270z318" at 305.272,182.376 h1.27
  text "4" at 188.718,179.201 h1.27
  text "125.98mil (3.200mm)" at 201.397,179.201 h1.27
  text "PTH" at 225.715,179.201 h1.27
  text "Round" at 236.396,179.201 h1.27
  text "L1-TOP - L6-BOT" at 251.901,179.201 h1.27
  text "Pad" at 277.055,179.201 h1.27
  text "Rounded" at 289.513,179.201 h1.27
  text "c650h320" at 305.272,179.201 h1.27
  text "6" at 188.718,176.026 h1.27
  text "40.00mil (1.016mm)" at 201.397,176.026 h1.27
  text "NPTH" at 225.715,176.026 h1.27
  text "Round" at 236.396,176.026 h1.27
  text "L1-TOP - L6-BOT" at 251.901,176.026 h1.27
  text "Pad" at 277.055,176.026 h1.27
  text "Rounded" at 289.513,176.026 h1.27
  text "c102hn102p102" at 305.272,176.026 h1.27
  text "8" at 188.718,172.851 h1.27
  text "65.00mil (1.651mm)" at 201.397,172.851 h1.27
  text "PTH" at 225.715,172.851 h1.27
  text "Round" at 236.396,172.851 h1.27
  text "L1-TOP - L6-BOT" at 251.901,172.851 h1.27
  text "Pad" at 277.055,172.851 h1.27
  text "Rounded" at 289.513,172.851 h1.27
  text "c254h165" at 305.272,172.851 h1.27
  text "16" at 188.718,169.676 h1.27
  text "67.00mil (1.702mm)" at 201.397,169.676 h1.27
  text "PTH" at 225.715,169.676 h1.27
  text "Round" at 236.396,169.676 h1.27
  text "L1-TOP - L6-BOT" at 251.901,169.676 h1.27
  text "Pad" at 277.055,169.676 h1.27
  text "Rounded" at 289.513,169.676 h1.27
  text "c254h170" at 305.272,169.676 h1.27
  text "18" at 188.718,166.501 h1.27
  text "37.40mil (0.950mm)" at 201.397,166.501 h1.27
  text "PTH" at 225.715,166.501 h1.27
  text "Round" at 236.396,166.501 h1.27
  text "L1-TOP - L6-BOT" at 251.901,166.501 h1.27
  text "Pad" at 277.055,166.501 h1.27
  text "Rounded" at 289.513,166.501 h1.27
  text "(Mixed)" at 305.272,166.501 h1.27
  text "A" at 177.427,166.298 h1.41
  text "20" at 188.718,163.326 h1.27
  text "41.34mil (1.050mm)" at 201.397,163.326 h1.27
  text "PTH" at 225.715,163.326 h1.27
  text "Round" at 236.396,163.326 h1.27
  text "L1-TOP - L6-BOT" at 251.901,163.326 h1.27
  text "Pad" at 277.055,163.326 h1.27
  text "Rectangle" at 289.513,163.326 h1.27
  text "s200h105" at 305.272,163.326 h1.27
  text "254" at 188.718,160.151 h1.27
  text "31.50mil (0.800mm)" at 201.397,160.151 h1.27
  text "PTH" at 225.715,160.151 h1.27
  text "Round" at 236.396,160.151 h1.27
  text "L1-TOP - L6-BOT" at 251.901,160.151 h1.27
  text "Pad" at 277.055,160.151 h1.27
  text "(Mixed)" at 289.513,160.151 h1.27
  text "(Mixed)" at 305.272,160.151 h1.27
  text "296" at 188.718,156.976 h1.27
  text "8.00mil (0.203mm)" at 201.397,156.976 h1.27
  text "PTH" at 225.715,156.976 h1.27
  text "Round" at 236.396,156.976 h1.27
  text "L1-TOP - L6-BOT" at 251.901,156.976 h1.27
  text "Via" at 277.055,156.976 h1.27
  text "Rounded" at 289.513,156.976 h1.27
  text "v41h20m0mx0" at 305.272,156.976 h1.27
  text "643 Total" at 188.718,153.801 h1.27
Doc-Assy-Top:
  lines w0.092: -14.241,8.948 -10.551,8.948 ; -14.241,48.155 -10.551,48.155 ; -14.241,87.361 -10.551,87.361 ; 32.807,-26.568 32.807,-22.878 ; 32.807,119.188 32.807,122.878 ; 83.545,-26.568 83.545,-22.878 ; 83.545,119.188 83.545,122.878 ; 98.305,-26.568 181.331,-26.568 ; 122.358,-22.873 122.358,-9.723 177.625,-9.723 ; 122.358,-18.435 177.625,-18.435 ; 130.698,-22.873 130.698,-18.435 ; 134.283,-26.568 134.283,-22.878 ; 134.283,119.188 134.283,122.878 ; 143.638,-22.873 143.638,-18.435 ; 146.225,-18.43 146.225,-9.723 ; 162.766,-22.873 162.766,-18.435 ; 177.641,8.948 181.331,8.948 ; 177.641,48.155 181.331,48.155 ; 177.641,87.361 181.331,87.361 ; 181.331,-26.568 -14.241,-26.568 -14.241,122.878 181.331,122.878 181.331,-26.568 ; -10.551,-22.878 177.641,-22.878 177.641,119.188 -10.551,119.188 -10.551,-22.878
  text "1" at 7.002,120.445 h1.29
  text "2" at 57.752,120.445 h1.29
  text "3" at 108.397,120.445 h1.29
  text "4" at 159.154,120.445 h1.29
  text "A" at -12.915,105.295 h1.29
  text "A" at 179.082,105.295 h1.29
  text "B" at -12.915,66.088 h1.29
  text "B" at 179.082,66.088 h1.29
  text "C" at -12.915,26.882 h1.29
  text "C" at 179.082,26.882 h1.29
  text "TITLE:" at 123.79,-11.175 h0.83
  text "Opal Kelly" at 147.677,-11.756 h1.29
  text "D" at -12.915,-12.233 h1.29
  text "D" at 179.082,-12.233 h1.29
  text "13500 SW 72nd Ave Suite 100" at 147.677,-13.934 h1.29
  text "Portland, OR 97223" at 147.677,-15.749 h1.29
  text "'.Part_Number' / Assembly Drawing" at 124.387,-15.78 h1.29
  text "www.opalkelly.com" at 147.677,-17.564 h1.29
  text "(Top)" at 124.387,-17.882 h1.29
  text "REV:" at 123.384,-19.665 h0.83
  text "SIZE:" at 131.823,-19.665 h0.83
  text "ENGINEER:" at 144.763,-19.665 h0.83
  text "DATE:" at 163.892,-19.665 h0.83
  text "'.PCB_Revision'XX" at 124.51,-21.916 h1.29
  text "ANSI A" at 132.949,-21.916 h1.29
  text "NDK" at 145.888,-21.916 h1.29
  text ".PRINT_DATE" at 165.017,-21.916 h1.29
  text "1" at 7.002,-25.427 h1.29
  text "2" at 57.752,-25.427 h1.29
  text "3" at 108.397,-25.427 h1.29
  text "4" at 159.154,-25.427 h1.29
Doc-Assy-Bot:
  lines w0.092: -14.235,8.969 -10.545,8.969 ; -14.235,48.176 -10.545,48.176 ; -14.235,87.384 -10.545,87.384 ; -10.53,-18.415 44.739,-18.415 ; -10.53,-9.702 44.739,-9.702 44.739,-22.853 ; 4.329,-22.853 4.329,-18.415 ; 20.871,-18.409 20.871,-9.702 ; 23.458,-22.853 23.458,-18.415 ; 32.814,-26.548 32.814,-22.858 ; 32.814,119.211 32.814,122.901 ; 36.398,-22.853 36.398,-18.415 ; 68.792,-26.548 -14.235,-26.548 ; 83.552,-26.548 83.552,-22.858 ; 83.552,119.211 83.552,122.901 ; 134.291,-26.548 134.291,-22.858 ; 134.291,119.211 134.291,122.901 ; 177.65,8.969 181.34,8.969 ; 177.65,48.176 181.34,48.176 ; 177.65,87.384 181.34,87.384 ; -14.235,-26.548 -14.235,122.901 181.34,122.901 181.34,-26.548 -14.235,-26.548 ; -10.545,-22.858 -10.545,119.211 177.65,119.211 177.65,-22.858 -10.545,-22.858
  text "4" at 7.942,120.468 h1.29
  text "3" at 58.7,120.468 h1.29
  text "2" at 109.346,120.468 h1.29
  text "1" at 160.097,120.468 h1.29
  text "A" at -11.987,105.317 h1.29
  text "A" at 180.014,105.317 h1.29
  text "B" at -11.987,66.11 h1.29
  text "B" at 180.014,66.11 h1.29
  text "C" at -11.987,26.903 h1.29
  text "C" at 180.014,26.903 h1.29
  text "TITLE:" at 43.306,-11.154 h0.83
  text "Opal Kelly" at 19.419,-11.735 h1.29
  text "D" at -11.987,-12.212 h1.29
  text "D" at 180.014,-12.212 h1.29
  text "13500 SW 72nd Ave Suite 100" at 19.419,-13.913 h1.29
  text "Portland, OR 97223" at 19.419,-15.729 h1.29
  text "'.Part_Number' / Assembly Drawing" at 42.709,-15.76 h1.29
  text "www.opalkelly.com" at 19.419,-17.544 h1.29
  text "(Bottom)" at 42.709,-17.862 h1.29
  text "DATE:" at 3.204,-19.645 h0.83
  text "ENGINEER:" at 22.333,-19.645 h0.83
  text "SIZE:" at 35.273,-19.645 h0.83
  text "REV:" at 43.712,-19.645 h0.83
  text ".PRINT_DATE" at 2.079,-21.895 h1.29
  text "NDK" at 21.208,-21.895 h1.29
  text "ANSI A" at 34.148,-21.895 h1.29
  text "'.PCB_Revision'XX" at 42.587,-21.895 h1.29
  text "4" at 7.942,-25.407 h1.29
  text "3" at 58.7,-25.407 h1.29
  text "2" at 109.346,-25.407 h1.29
  text "1" at 160.097,-25.407 h1.29
Assy Top:
  text "SHIELD1" at 121.514,39.472 h1.27
  text "SHIELD2" at 121.615,20.98 h1.27
Doc-Fab:
  lines w0.127: 235.966,-24.718 235.966,2.108 351.261,2.108 ; 235.966,-5.512 280.67,-5.512 ; 235.966,-2.718 280.67,-2.718 ; 235.966,0.076 280.67,0.076 ; 246.634,-24.718 246.634,2.108 ; 280.67,-24.718 280.67,2.108 ; 280.67,-19.736 351.282,-19.736 ; 280.67,-8.56 351.261,-8.56 ; 294.894,-24.718 294.894,-19.736 ; 312.166,-19.736 312.166,-8.56 ; 328.676,-24.718 328.676,-19.736
  lines w0.14: -61.819,35.946 -56.237,35.946 ; -61.819,102.238 -56.237,102.238 ; -61.819,168.531 -56.237,168.531 ; 7.962,-30.347 7.962,-24.764 ; 7.962,229.24 7.962,234.823 ; 77.744,-30.347 77.744,-24.764 ; 77.744,229.24 77.744,234.823 ; 147.525,-30.347 147.525,-24.764 ; 147.525,229.24 147.525,234.823 ; 217.307,-30.347 217.307,-24.764 ; 217.307,229.24 217.307,234.823 ; 287.088,-30.347 287.088,-24.764 ; 287.088,229.24 287.088,234.823 ; 351.287,35.946 356.87,35.946 ; 351.287,102.238 356.87,102.238 ; 351.287,168.531 356.87,168.531 ; -61.819,-30.347 356.87,-30.347 356.87,234.823 -61.819,234.823 -61.819,-30.347 ; -56.237,-24.764 351.287,-24.764 351.287,229.24 -56.237,229.24 -56.237,-24.764
  text "1" at -27.449,231.194 h1.95
  text "2" at 42.211,231.194 h1.95
  text "3" at 111.695,231.194 h1.95
  text "4" at 181.663,231.194 h1.95
  text "5" at 251.416,231.194 h1.95
  text "6" at 321.337,231.194 h1.95
  text "A" at -59.726,199.29 h1.95
  text "A" at 353.381,199.29 h1.95
  text "B" at -59.726,132.858 h1.95
  text "B" at 353.381,132.858 h1.95
  text "C" at -59.726,66.566 h1.95
  text "C" at 353.381,66.566 h1.95
  text "REVISION:" at 236.703,0.584 h1.02
  text "DESCRIPTION:" at 247.625,0.584 h1.02
  text "D" at -59.726,0.413 h1.95
  text "D" at 353.381,0.413 h1.95
  text "PART NUMBER:" at 282.702,-1.448 h1.91
  text "AXX" at 236.728,-1.956 h1.27
  text "20181127 - Initial Release" at 247.65,-1.956 h1.27
  text "BXX" at 236.728,-4.75 h1.27
  text "20181221 - Replace QSE with QTE" at 247.65,-4.75 h1.27
  text "'.Part_Number'-PCB-'.PCB_Revision'XX" at 283.21,-8.56 h3.3
  text "TITLE:" at 282.194,-10.592 h1.02
  text "Opal Kelly" at 313.69,-11.1 h1.52
  text "13500 SW 72nd Ave Suite 100" at 313.69,-13.64 h1.52
  text "Portland, OR 97223" at 313.69,-16.18 h1.52
  text "'.Part_Number' / Fabrication Drawing" at 283.21,-18.212 h1.52
  text "www.opalkelly.com" at 313.69,-18.72 h1.52
  text "SIZE:" at 282.194,-21.26 h1.02
  text "ENGINEER:" at 296.418,-21.26 h1.02
  text "DATE:" at 329.946,-21.26 h1.02
  text "ANSI A" at 283.21,-23.8 h1.52
  text "NDK" at 297.434,-23.8 h1.52
  text ".PRINT_DATE" at 330.962,-23.8 h1.52
  text "1" at -27.449,-28.393 h1.95
  text "2" at 42.211,-28.393 h1.95
  text "3" at 111.695,-28.393 h1.95
  text "4" at 181.663,-28.393 h1.95
  text "5" at 251.416,-28.393 h1.95
  text "6" at 321.337,-28.393 h1.95

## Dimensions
0,100 to 135,95 on Dimensions
0,0 to 0,100 on Dimensions
0,100 to 5,95 on Dimensions
0,100 to 140,100 on Dimensions
5,5 to 0,0 on Dimensions
0,0 to 0,100 on Dimensions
